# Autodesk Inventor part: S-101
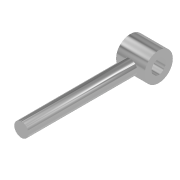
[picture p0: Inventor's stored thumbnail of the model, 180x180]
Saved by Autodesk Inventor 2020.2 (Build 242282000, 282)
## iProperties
Created: 2014-01
Part Number: S-101
Material: Ogólny
Document SubType Name: Modeling
Designer: F.Stasiak
Density: 1 g/cm^3
Appearance: Chrom - polerowany
Manager: www.cadconsulting.pl
Company: Fabian Stasiak CAD Consulting
Author: F.Stasiak
Subject: Zbiór ćwiczeń. Autodesk Inventor 2020. Kurs podstawowy
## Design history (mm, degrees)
sketch "Szkic1"
  geometry: C1 r 15 at (0, 0); 1 further point
  constraints: 1 centre point, 1 coincident
  dimensions: "d0" = 30 diameter of C1
extrude "Wyciągnięcie proste1" new body sketch "Szkic1" distance "d1" = 230; taper "d2" = 0 deg
sketch "Szkic2" dims "d3" = 60
  geometry: C1 r 15 at (0, -30); 2 further points
  constraints: 2 vertical alignment, 1 centre point, 1 coincident, 2 other
  dimensions: "d4" = 30 diameter of C1
extrude "Wyciągnięcie proste2" join sketch "Szkic2" stored distance "d5" = 60; taper "d6" = 0 deg
node "Bryła1"
